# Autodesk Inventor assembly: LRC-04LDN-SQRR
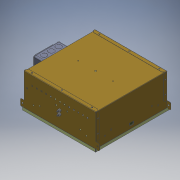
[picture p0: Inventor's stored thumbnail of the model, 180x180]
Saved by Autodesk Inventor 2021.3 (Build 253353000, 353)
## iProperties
description: 0:0:Regressed Lens 4" Downlight - COB LED
manufacturer: 0:0:The Kirlin Company
model: 0:0:LRC-04LDN
url: 0:0:
Part Number: LRC-04LDN-SQRR
Document SubType Name: Assembly
Designer: JChurch
load_classification: Lighting
motor: 0 ul
Author: JChurch
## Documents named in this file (6)
- X:\Revit Files\0000-Un-Zipped\COB\LRC-04LDN-SQR\LRC-04LDN-SQRR.iam
- X:\INVENTOR\830\830557-00-00.iam
- X:\INVENTOR\881\881088-00-00.iam
- X:\INVENTOR\750\750206-00-00.iam
- X:\INVENTOR\725\725292-00-00.ipt
- X:\Revit Files\0000-Un-Zipped\COB\LRC-04LDN-SQR\LRC-04LDN-SQRR_Substitute_1.ipt
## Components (5 placed, 5 different names)
1. 830557-00-00:1 [sub-assembly] — Mate:1, Mate:2, Mate:3, Mate:4, Tangent:1, Angle:1, Mate:7
2. 881088-00-00:1 [sub-assembly] — Mate:4, Tangent:1, Angle:1
3. 750206-00-00:1 [sub-assembly] — Mate:5, Mate:6, Flush:1, Mate:7, Mate:8, Mate:9
4. 725292-00-00:1 — Mate:5, Mate:6, Flush:1
5. LRC-04LDN-SQRR_Substitute_1:1
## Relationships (12: Mate 9, Tangent 1, Angle 1, Flush 1)
- Mate:1: 830557-00-00:1
- Mate:2: 830557-00-00:1
- Mate:3: 830557-00-00:1
- Mate:4: 830557-00-00:1 ↔ 881088-00-00:1
- Tangent:1: 830557-00-00:1 ↔ 881088-00-00:1
- Angle:1: 830557-00-00:1 ↔ 881088-00-00:1
- Mate:5: 750206-00-00:1 ↔ 725292-00-00:1
- Mate:6: 750206-00-00:1 ↔ 725292-00-00:1
- Flush:1: 750206-00-00:1 ↔ 725292-00-00:1
- Mate:7: 830557-00-00:1 ↔ 750206-00-00:1
- Mate:8: 750206-00-00:1
- Mate:9: 750206-00-00:1
